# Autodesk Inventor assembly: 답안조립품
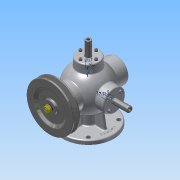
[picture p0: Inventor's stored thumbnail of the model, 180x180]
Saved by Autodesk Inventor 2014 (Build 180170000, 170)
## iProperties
Created: 2016-01
Part Number: 답안조립품
Document SubType Name: Assembly
Designer: Administrator
Mass: 3770.67 g
Surface Area: 2410.99 cm^2
Volume: 903.657 cm^3
Density: 4.17267 g/cm^3
Author: Administrator
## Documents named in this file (17)
- C:\Users\Administrator\Desktop\360108V1016\답안조립품.iam
- C:\Users\Administrator\Desktop\360108V1016\본체.ipt
- C:\Users\Administrator\Desktop\360108V1016\V-벨트풀리.ipt
- C:\Users\Administrator\Desktop\360108V1016\너트-M8x1.ipt
- C:\Users\Administrator\Desktop\360108V1016\뒤커버.ipt
- C:\Users\Administrator\Desktop\360108V1016\베어링- 6202.ipt
- C:\Users\Administrator\Desktop\360108V1016\본체커버.ipt
- C:\Users\Administrator\Desktop\360108V1016\볼트 M4x0.7.ipt
- C:\Users\Administrator\Desktop\360108V1016\슬라이드 커버.ipt
- C:\Users\Administrator\Desktop\360108V1016\슬라이드.ipt
- C:\Users\Administrator\Desktop\360108V1016\앞커버.ipt
- C:\Users\Administrator\Desktop\360108V1016\오일실.ipt
- C:\Users\Administrator\Desktop\360108V1016\와셔 8x17.ipt
- C:\Users\Administrator\Desktop\360108V1016\축.ipt
- C:\Users\Administrator\Desktop\360108V1016\키-4x4.ipt
- C:\Users\Administrator\Desktop\360108V1016\15-스프링.ipt
- C:\Users\Administrator\Desktop\360108V1016\16-스프링.ipt
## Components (20 placed, 4 different names)
1. M4x0.7x12:5
2. 15-스프링:1
3. 16-스프링:1
4. V-벨트풀리:1 — 플러쉬:2, 각도:2
5. M4x0.7x12:4
6. M4x0.7x12:6
7. M4x0.7x12:7
8. M4x0.7x12:8
9. M4x0.7x12:1
10. M4x0.7x12:9
11. M4x0.7x12:10
12. M4x0.7x12:11
13. M4x0.7x12:2
14. M4x0.7x12:12
15. M4x0.7x12:13
16. M4x0.7x12:14
17. M4x0.7x12:3
18. M4x0.7x12:15
19. M4x0.7x12:16
20. M4x0.7x12:17
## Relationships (2: Flush 1, Angle 1)
- 플러쉬:2 [Flush]: V-벨트풀리:1
- 각도:2 [Angle]: V-벨트풀리:1
